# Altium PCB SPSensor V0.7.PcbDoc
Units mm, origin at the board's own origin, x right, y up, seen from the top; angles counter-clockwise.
Board outline 97.48 x 57.45 mm, 2 copper layers (TopLayer, BottomLayer), stack 1.671 mm thick; 111 components, 69 nets, 358 pads, 144 vias.
Unrouted connection lines stored in the file: 1.
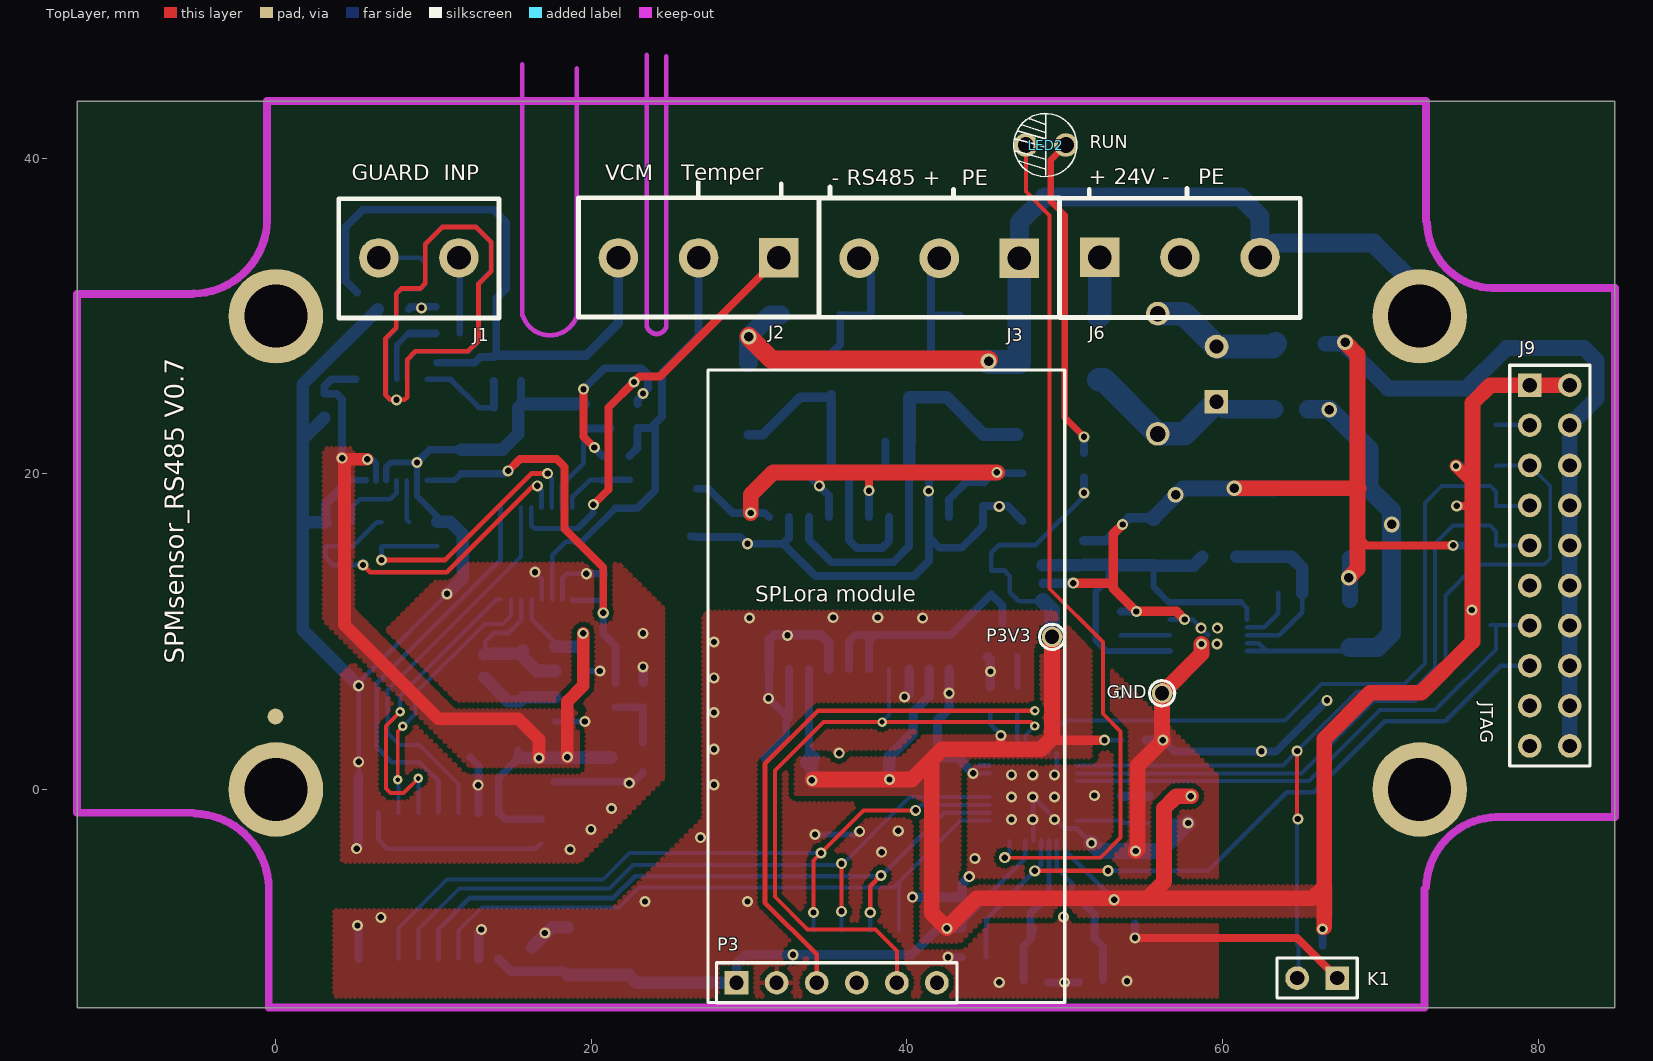
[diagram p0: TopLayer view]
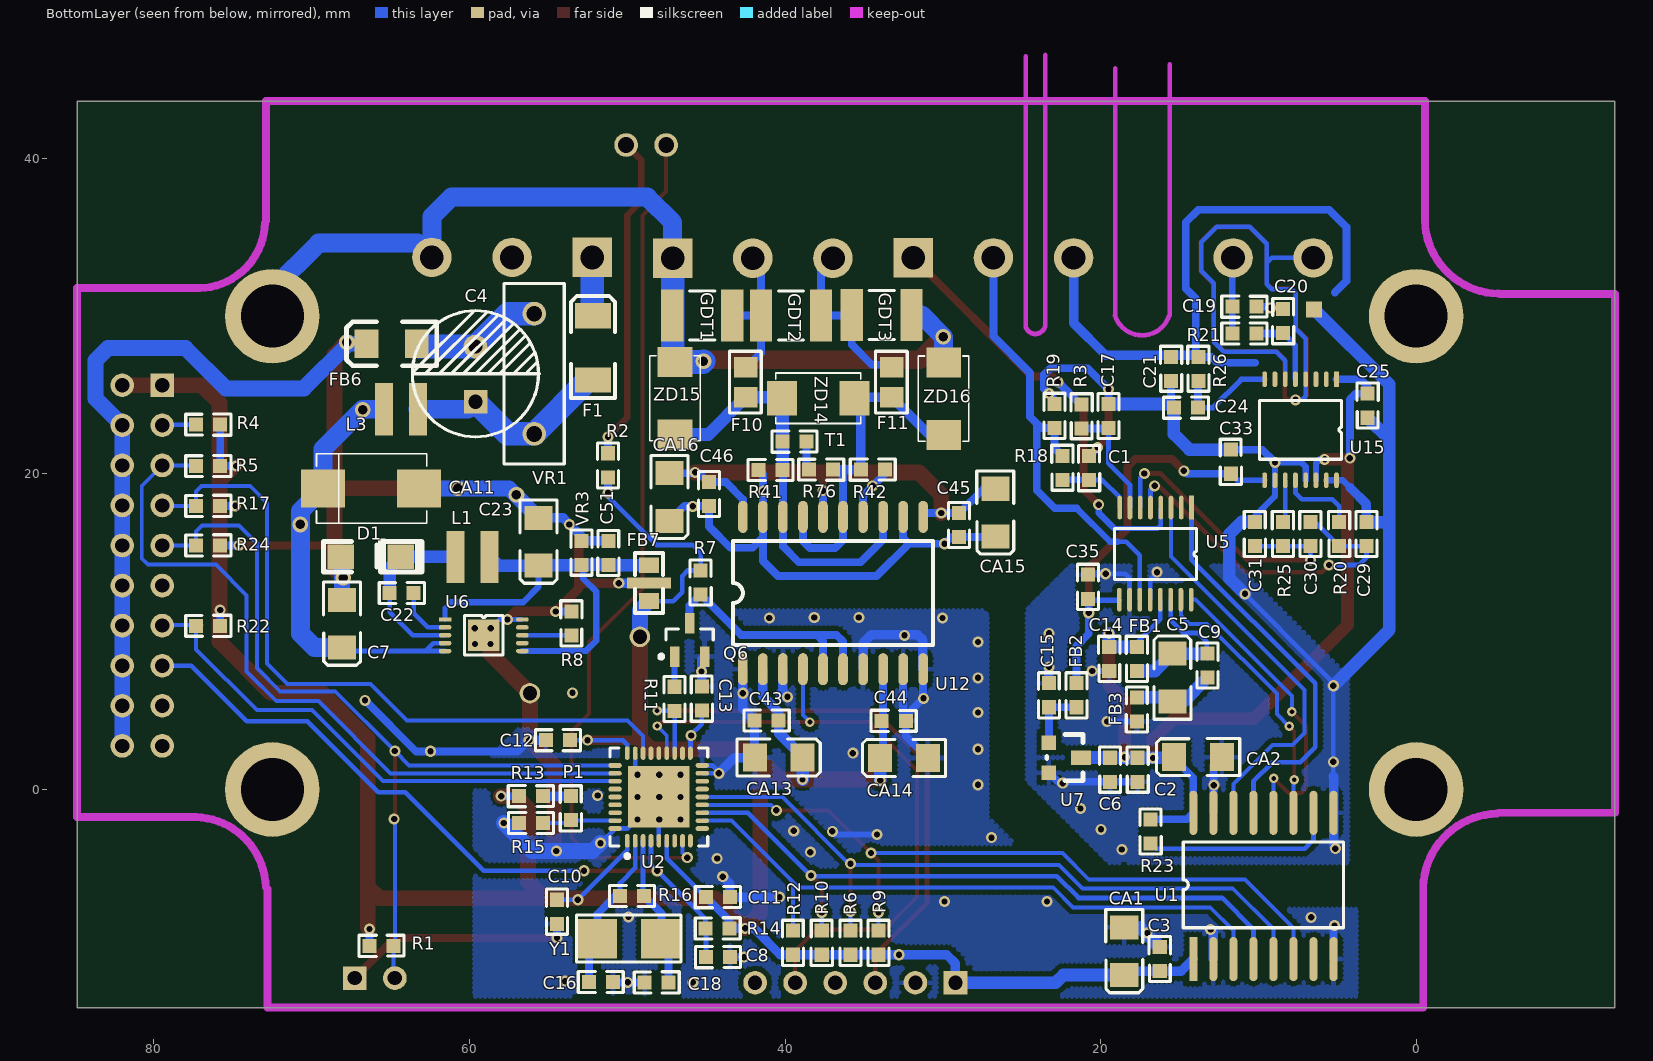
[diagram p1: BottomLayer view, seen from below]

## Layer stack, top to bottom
TopLayer: signal copper 0.0356
Dielectric: core 1.6, FR-4, Dk 4.8
BottomLayer: signal copper 0.0356

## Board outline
-12.6,-13.825 84.875,-13.825 84.875,43.625 -12.6,43.625

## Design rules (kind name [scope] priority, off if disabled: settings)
Clearance Clearance_poly [InPolygon] p1: gap=0.3
Clearance [All] p2: gap=0.15
ComponentClearance [All] p1: gap=0.15 collisioncheckmode=3 verticalgap=0.254 showdistances=FALSE
FabricationTestPointUsage TestPointUsage [All] p1: valid=0 allowmultiple=FALSE
FabricationTestpoint Testpoint [All] p1: side=3 testpointundercomponent=TRUE minsize=1.016 maxsize=2.54 preferedsize=1.524 minholesize=0.508 maxholesize=1.016 preferedholesize=0.813 testpointgrid=0.025 allowsidetop=TRUE allowsidebottom=TRUE usegrid=TRUE gridtolerance=0
HoleSize [All] p1: absolutevalues=TRUE maxlimit=10 minlimit=0.025 maxpercent=80.000 minpercent=20.000
MinimumSolderMaskSliver [All] p1: minsoldermaskwidth=0.15
PlaneClearance [All] p1: clearance=0.2
PlaneConnect [All] p1: planeconnectstyle=Relief reliefexpansion=0.3 reliefentries=4 reliefconductorwidth=0.3 reliefairgap=0.3
PolygonConnect PolygonConnect_via [IsVia] p1: connectstyle=Direct reliefconductorwidth=0.254 reliefentries=4 polygonreliefangle="90 Angle"
PolygonConnect [All] p2: connectstyle=Relief reliefconductorwidth=0.3 reliefentries=4 polygonreliefangle="90 Angle"
RoutingVias [All] p1: holewidth=0.305 width=0.61 viastyle="Through Hole" minholewidth=0.254 minwidth=0.508 maxholewidth=2 maxwidth=5
SilkToSilkClearance [All] p1: silktosilkclearance=0
SilkscreenOverComponentPads [All] p1: minsilkscreentomaskgap=0
SolderMaskExpansion [All] p1: expansion=0.102
Width [All] p1: maxlimit=5.08 minlimit=0.1 preferedwidth=0.254
19 further rules are at their usual default settings.

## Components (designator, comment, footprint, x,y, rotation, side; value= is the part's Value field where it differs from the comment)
C1 "1uF" SM0603 20.775,20.375 r90 bottom
C2 "0.1uF" SM0603 17.6,1.25 r270 bottom
C3 "0.1uF" SM0603 16.2,-10.75 r270 bottom
C4 "100uF/100V" PCAP_3.5_8 59.625,24.575 r90 bottom
C5 "10uF" SM1206 15.45,7.1 r90 bottom
C6 "4.7uF" SM0603 19.35,1.25 r270 bottom
C7 "4.7uF/50V" SM1206 68.075,10.5 r270 bottom
C8 "0.1uF" SM0603 44.25,-10.575 r180 bottom
C9 "0.1uF" SM0603 13.175,7.85 r270 bottom
C10 "0.1uF" SM0603 54.405,-7.75 r270 bottom
C11 "0.1uF" SM0603 44.255,-6.775 r180 bottom
C12 "0.1uF" SM0603 54.4,3.075 r0 bottom
C13 "0.1uF" SM0603 45.33,5.765 r90 bottom
C14 "0.1uF" SM0603 19.4,8.275 r270 bottom
C15 "1uF" SM0603 23.325,5.975 r90 bottom
C16 "22pF" SM0603 51.675,-12.15 r180 bottom
C17 "1uF" SM0603 19.551,23.676 r90 bottom
C18 "22pF" SM0603 48.14,-12.275 r0 bottom
C19 "1uF/50V" SM0603 10.885,30.65 r180 bottom
C20 "1uF/50V" SM0603 8.475,29.69 r90 bottom
C21 "0.1uF" SM0603 15.475,26.66 r270 bottom
C22 "0.47uF" SM0603 64.3,12.4 r0 bottom
C23 "22uF" SM1206 55.625,15.7 r270 bottom
C24 "0.1uF" SM0603 14.59,24.15 r0 bottom
C25 "0.1uF" SM0603 3.025,24.325 r270 bottom
C29 "1uF" SM0603 3.1,16.185 r270 bottom
C30 "100pF" SM0603 6.65,16.185 r270 bottom
C31 "1uF" SM0603 10.275,16.2 r90 bottom
C33 "0.1uF" SM0603 11.8,20.775 r90 bottom
C35 "0.1uF" SM0603 20.85,12.85 r90 bottom
C43 "0.1uF" SM0603 41.175,4.325 r0 bottom
C44 "0.1uF" SM0603 33.11,4.4 r180 bottom
C45 "0.1uF" SM0603 29.025,16.775 r90 bottom
C46 "0.1uF" SM0603 44.775,18.725 r270 bottom
C51 "0.1uF" SM0603 51.25,15 r90 bottom
CA1 "10uF" SM1206 18.5,-10.25 r270 bottom
CA2 "10uF" SM1206 13.825,2.05 r0 bottom
CA11 "47uF/50V" D 69.3,19.075 r180 bottom
CA13 "10uF" SM1206 40.4,2.025 r180 bottom
CA14 "10uF" SM1206 32.465,2 r0 bottom
CA15 "10uF" SM1206 26.675,17.55 r270 bottom
CA16 "10uF" SM1206 47.325,18.535 r270 bottom
D1 "CD1607-B140" 1206D 67.967,14.75 r180 bottom
F1 "1210L005WR" 1808C 52.175,26.088 r90 bottom
F10 "FUSE1" SM0805 42.475,25.8 r90 bottom
F11 "FUSE1" SM0805 33.225,25.8 r90 bottom
FB1 "BLM18PG600SN1" SM0603 17.65,8.275 r270 bottom
FB2 "BLM18PG600SN1" SM0603 21.575,5.975 r90 bottom
FB3 "BLM18PG600SN1" SM0603 17.75,5.075 r90 bottom
FB6 "BLM31PG500SN1" 1206 66.4,28.25 r0 bottom
FB7 "NFM21PC105B1C3" NFM21PC105 48.625,14.225 r270 bottom
GDT1 "SMD1812-091" 1812 45.25,30.05 r180 bottom
GDT2 "SMD1812-091" 1812 39.625,30.05 r0 bottom
GDT3 "SMD1812-091" 1812 33.875,30.075 r180 bottom
GND "TestPoint" "test point" 56.175,6.1 r90 top
J1 "PH2-5.08mm" PH2-5.08mm 6.525,33.7 r0 top locked
J2 "PH3-5.08mm" PH3-5.08mm 31.875,33.7 r180 top
J3 "PH3-5.08mm" PH3-5.08mm 47.125,33.675 r180 top locked
J6 "PH3-5.08mm" PH3-5.08mm 52.225,33.725 r0 top
J9 "JTAG" HDR2X10 79.475,25.625 r270 top
K1 "KEY1" HDR1x2 67.275,-11.955 r180 top (schematic designator R1)
L1 "LPS3010-472ML" LPS3010 60.885,14.75 r180 bottom
L3 "LPS3010-472ML" LPS3010 63.275,24.1 r0 bottom
LED2 "RUN" LED 50.075,40.85 r180 top
P1 "NC" sm0603 53.63,-1.185 r90 bottom
P3 "Header 6" HDR1X6 29.2,-12.25 r0 top
P3V3 "TestPoint" "test point" 49.2,9.675 r90 top
Q6 "MMBT3904" SOT23_N 46.05,9.475 r90 bottom
R1 "10K" SM0603 65.575,-9.855 r180 bottom
R2 "560R" SM0603 51.275,20.55 r90 bottom
R3 "10K" SM0603 21.151,23.651 r270 bottom
R4 "10K" SM0603 76.565,23.075 r0 bottom
R5 "10K" SM0603 76.565,20.45 r0 bottom
R6 "100K" SM0603 35.901,-9.713 r90 bottom
R7 "4.7K" SM0603 45.4,13.125 r90 bottom
R8 "49.9K" SM0603 53.5,10.525 r270 bottom
R9 "100K" SM0603 34.126,-9.713 r90 bottom
R10 "100K" SM0603 37.726,-9.713 r90 bottom
R11 "1K" SM0603 47.055,5.75 r90 bottom
R12 "100K" SM0603 39.551,-9.713 r90 bottom
R13 "1K" SM0603 56.105,-0.375 r180 bottom
R14 "10K" SM0603 44.275,-8.85 r0 bottom
R15 "100K" SM0603 56.09,-2.075 r180 bottom
R16 "10M" SM0603 49.7,-6.7 r180 bottom
R17 "10K" SM0603 76.565,17.925 r0 bottom
R18 "10K" SM0603 22.375,20.385 r270 bottom
R19 "5K,0.1%" SM0603 22.875,23.675 r270 bottom
R20 "10K" SM0603 4.825,16.185 r270 bottom
R21 "10M" SM0603 10.885,28.95 r180 bottom
R22 "10K" SM0603 76.565,10.325 r0 bottom
R23 "4.7K" SM0603 16.875,-2.65 r90 bottom
R24 "NC" SM0603 76.565,15.425 r0 bottom
R25 "10K" SM0603 8.4,16.185 r270 bottom
R26 "10K" SM0603 13.75,26.66 r270 bottom
R41 "47K" SM0603 40.91,20.3 r180 bottom
R42 "47K" SM0603 34.435,20.325 r180 bottom
R76 "120R" SM0603 37.715,20.225 r0 bottom
T1 "" SM0603 39.4,22.1 r180 bottom
U1 "ADuM5401ARWZ" ADUM1401 14.125,-10.75 r90 bottom
U2 "STM32F103TBU6" VFQN36_V 48,-0.475 r90 bottom locked
U5 "AD7793BRU" AD7793 16.525,14.95 r270 bottom
U6 "LT3971IMSE-3.3" LT3971 59.1,9.775 r270 bottom
U7 "AD1584BRTZ" SOT-23 21.13,0.639 r270 bottom
U12 "ADM2587E" SOL-20 42.675,7.625 r90 bottom
U15 "LMP91200" LMP91200 7.325,22.8 r0 bottom
VR1 "14D101K" RAD-0.3 55.9,26.35 r90 bottom
VR3 "V3.5MLA0603N" SM0603 52.85,15 r270 bottom (schematic designator VA2)
Y1 "8MHz" CY5.4X4.6 51.875,-9.45 r180 bottom
ZD14 "SMBJ12" ZD 40.2,24.8 r180 bottom (schematic designator ZD16)
ZD15 "SMBJ12" ZD 46.975,22.5 r90 bottom
ZD16 "SMBJ12" ZD 29.95,27.075 r270 bottom

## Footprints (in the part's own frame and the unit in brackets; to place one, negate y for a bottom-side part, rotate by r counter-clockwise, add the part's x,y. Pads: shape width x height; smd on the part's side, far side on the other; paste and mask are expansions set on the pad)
1206 [mm]
  rect 1.5x1.8 smd: 1(-3.048,0) 2(0.127,0)
  silkscreen extent -4.32,-1.4 1.4,1.4
1206D [mm]
  rect 1.7x1.524 smd: 1(-0.19,0.003) 2(3.61,0.003)
  silkscreen extent -1.3,-0.97 4.96,0.99
1808C [mm]
  rect 1.6x2.3 smd: 1(3.937,0) 2(-0.127,0)
  silkscreen extent -1.27,-1.4 5.21,1.4
1812 [mm] "Chip Capacitor, Body 4.5x3.2mm, IPC High Density"
  rect 1.4x3.3 smd: 1(-1.9,0) 2(1.9,0)
  silkscreen extent -0.8,-1.55 0.8,1.55, body extent -2.4,-1.7 2.4,1.7, height 1.4
AD7793 [mm]
  rect 1.5x0.3 smd: 1(-2.921,2.286)
  oval 1.5x0.3 smd: 2(-2.921,1.636) 3(-2.921,0.986) 4(-2.921,0.336) 5(-2.921,-0.314) 6(-2.921,-0.964) 7(-2.921,-1.614) 8(-2.921,-2.264) 9(2.921,-2.286) 10(2.921,-1.636) 11(2.921,-0.986) 12(2.921,-0.336) 13(2.921,0.314) 14(2.921,0.964) 15(2.921,1.614) 16(2.921,2.264)
  silkscreen extent -1.59,-2.59 1.64,2.61
ADUM1401 [mm]
  rect 2.8x0.51 smd: 1(0,0)
  oval 2.8x0.51 smd: 2(0,-1.27) 3(0,-2.54) 4(0,-3.81) 5(0,-5.08) 6(0,-6.35) 7(0,-7.62) 8(0,-8.89) 9(9.271,-8.89) 10(9.271,-7.62) 11(9.271,-6.35) 12(9.271,-5.08) 13(9.271,-3.81) 14(9.271,-2.54) 15(9.271,-1.27) 16(9.271,0)
  silkscreen extent 1.99,-9.53 7.43,0.63
CY5.4X4.6 [mm]
  rect 2.5x2.5 smd: 1(-0.025,0) 2(4,0)
  silkscreen extent -1.35,-1.49 5.28,1.49
D [mil]
  rect 110x94.49 smd: 1(0,0) 2(240,0)
  silkscreen extent -16,-87 260,87
HDR1x2 [mm] "Connector; Header; 2 Position"
  rect 1.5x1.5 hole 0.9: 1(0,0)
  round 1.5 hole 0.9: 2(2.54,0)
  silkscreen extent -1.27,-1.27 3.81,1.27
HDR1X6 [mm] "Connector; Header; 6 Position"
  rect 1.5x1.5 hole 0.9: 1(0,0)
  round 1.5 hole 0.9: 2(2.54,0) 3(5.08,0) 4(7.62,0) 5(10.16,0) 6(12.7,0)
  silkscreen extent -1.27,-1.27 13.97,1.27
HDR2X10 [mm] "Connector; Header; 10x2 Position"
  rect 1.5x1.5 hole 0.9: 1(0,0)
  round 1.5 hole 0.9: 2(0,2.54) 3(2.54,0) 4(2.54,2.54) 5(5.08,0) 6(5.08,2.54) 7(7.62,0) 8(7.62,2.54) 9(10.16,0) 10(10.16,2.54) 11(12.7,0) 12(12.7,2.54) 13(15.24,0) 14(15.24,2.54) 15(17.78,0) 16(17.78,2.54) 17(20.32,0) 18(20.32,2.54) 19(22.86,0) 20(22.86,2.54)
  silkscreen extent -1.27,-1.27 24.13,3.81
LED [mm]
  round 1.5 hole 1: 1(0,0) 2(2.54,0)
  silkscreen extent -0.7,-2 3.3,2
LMP91200 [mm]
  rect 0.3x1 smd: 1(-2.275,-3.2)
  oval 0.3x1 smd: 2(-1.625,-3.2) 3(-0.975,-3.2) 4(-0.325,-3.2) 5(0.325,-3.2) 6(0.975,-3.2) 7(1.625,-3.2) 8(2.275,-3.2) 9(2.275,3.2) 10(1.625,3.2) 11(0.975,3.2) 12(0.325,3.2) 13(-0.325,3.2) 14(-0.975,3.2) 15(-1.625,3.2) 16(-2.275,3.2)
  silkscreen extent -2.6,-1.87 2.6,1.87
LPS3010 [mm]
  rect 1.14x3.3 smd: 1(0,0) 2(2.16,0)
LT3971 [mm]
  rect 0.28x0.8 smd: 1(-1,-2.45)
  oval 0.28x0.8 smd: 2(-0.5,-2.45) 3(0,-2.45) 4(0.5,-2.45) 5(1,-2.45) 6(1,2.45) 7(0.5,2.45) 8(0,2.45) 9(-0.5,2.45) 10(-1,2.45)
  rect 2x2 smd: 11(0,0)
  silkscreen extent -1.25,-1.21 1.25,1.22
NFM21PC105 [mm]
  rect 1x1.27 smd: 1(0.01,0.008) 2(2.286,0)
  rect 0.7x2.8 smd: 3(1.143,0)
  silkscreen extent -0.76,-0.89 3.05,0.89
PCAP_3.5_8 [mm]
  rect 1.5x1.5 hole 0.9: 1(0.001,-0.009)
  round 1.5 hole 0.9: 2(3.5,0)
  silkscreen extent -2.22,-4.06 5.78,4
PH2-5.08mm [mm]
  round 2.5 hole 1.5: 1(0,0) 2(5.08,0)
  silkscreen extent -2.54,-3.81 7.62,3.75
PH3-5.08mm [mm]
  rect 2.5x2.5 hole 1.5: 1(0,0)
  round 2.5 hole 1.5: 2(5.08,0) 3(10.16,0)
  silkscreen extent -2.54,-3.81 12.7,3.75
RAD-0.3 [mm] "Radial Cap, Thru-Hole; 2 Leads; 0.3 in Pin Spacing"
  round 1.5 hole 1: 1(-3.81,0) 2(3.81,0)
  silkscreen extent -5.71,-1.91 5.71,1.91
SM0603 [mil]
  rect 35x35 smd: 1(-30,-2) 2(30,-2)
  silkscreen extent -57,-28 56,24
sm0603 [mil]
  rect 35x35 smd: 1(-30,-2) 2(30,-2)
  silkscreen extent -57,-28 56,24
SM0805 [mm]
  rect 1.3x1.5 smd: 1(-0.933,0.022) 2(0.967,0.022)
  silkscreen extent -1.93,-0.97 1.98,1.04
SM1206 [mil]
  rect 60x70 smd: 1(59.5,0) 2(-59.5,0)
  silkscreen extent -104,-46 104,46
SOL-20 [mil]
  oval 80x24 smd: 1(0,0) 2(0,-50) 3(0,-100) 4(0,-150) 5(0,-200) 6(0,-250) 7(0,-300) 8(0,-350) 9(0,-400) 10(0,-450) 11(380,-450) 12(380,-400) 13(380,-350) 14(380,-300) 15(380,-250) 16(380,-200) 17(380,-150) 18(380,-100) 19(380,-50) 20(380,0)
  silkscreen extent 60,-475 320,25
SOT23_N [mm] "SOT23, 3-Leads, Body 2.9x1.3mm, Pitch 0.95mm, Lead Span 2.3mm, IPC Medium Density"
  rect 1.3x0.6 smd: 1(-1.05,0.95) 2(-1.05,-0.95) 3(1.05,0)
  silkscreen extent -1.17,-1.5 0.7,1.93, body extent -0.7,-1.5 0.7,1.5, height 1.1
SOT-23 [mil]
  rect 36x36 smd: 1(-91.86,-84.66) 2(-16.86,-84.66)
  rect 36x50 smd: 3(-53.86,-4.66)
  silkscreen extent -112,-90 3,0
"test point" [mm]
  round 1.3 hole 0.9: 1(0,0)
  silkscreen extent -0.8,-0.8 0.8,0.8
VFQN36_V [mm] "QFN, 36-Leads, Body 6x6mm, Pitch 0.5mm, ST Recommended"
  oval 0.85x0.3 smd: 1(-2.775,2) 2(-2.775,1.5) 3(-2.775,1) 4(-2.775,0.5) 5(-2.775,0) 6(-2.775,-0.5) 7(-2.775,-1) 8(-2.775,-1.5) 9(-2.775,-2) 19(2.775,-2) 20(2.775,-1.5) 21(2.775,-1) 22(2.775,-0.5) 23(2.775,0) 24(2.775,0.5) 25(2.775,1) 26(2.775,1.5) 27(2.775,2)
  oval 0.3x0.85 smd: 10(-2,-2.755) 11(-1.5,-2.755) 12(-1,-2.755) 13(-0.5,-2.755) 14(0,-2.755) 15(0.5,-2.755) 16(1,-2.755) 17(1.5,-2.755) 18(2,-2.755) 28(2,2.775) 29(1.5,2.775) 30(1,2.775) 31(0.5,2.775) 32(0,2.775) 33(-0.5,2.775) 34(-1,2.775) 35(-1.5,2.775) 36(-2,2.775)
  rect 3.9x3.9 smd: 37(0,0)
  silkscreen extent -3.87,-3.1 3.1,3.1, body extent -3.05,-3.05 3.05,3.05, height 1
ZD [mm]
  rect 1.9x2.2 smd: 1(0,0) 2(4.6,0)
  silkscreen extent -0.4,-1.6 5,1.6

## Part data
C1 C6 C7 C9 C14 C15 C17 C19 C20 C21 C22 C24 C25 C29 C30 C31 C33 C35 C51: library part CAP, "Capacitor"
C2 C3 C43 C44 C45 C46: library part CA, "电容"
C4: library part C, "Capacitor"
C5 CA11 CA13 CA14 CA15 CA16: library part CAPE, "极性电容"
C8: library part Cap, "Capacitor, X7R Ceramic"
C10 C11 C12 C13 C16 C18: library part Cap, "Capacitor"
C23: library part C, "极性电容"
CA1 CA2: library part CAPE, "Capacitor"
D1: library part DIODE, "Diode"
F1: library part FUSE1, "Fuse, 50mA"
F10 F11: "Fuse"
FB1 FB3 L1 L3: library part INDUCTOR
FB2 FB6 FB7: library part Inductor, "Inductor"
GDT1 GDT2 GDT3: library part BT90
J1 K1: library part "Header 2", "Header, 2-Pin"
J2 J3 J6: library part CON3, "Connector"
J9: library part "Header 10X2", "Header, 10-Pin, Dual row"
LED2: library part LED0, "Typical INFRARED GaAs LED"
P1: library part Header, "Header, 2-Pin, 2.54mm, 排针"
P3: "Header, 6-Pin"
Q6: "NPN Switching Transistor"
R1 R2 R7 R11 R16: library part Res2, "Resistor"
R3 R4 R5 R6 R9 R10 R12 R17 R18 R19 R20 R22 R24 R25 R26: library part RES, "电阻"
R8 R13 R14 R15 R23 R41 R42 R76: library part RE, "电阻"
R21: library part RES, "resistor"
T1: library part CON2, "Connector"
U1: library part ADUM1401, "1Mbps Data Rate, 100ns Propagation delay"
U2: library part STM32F103T8U6, "STM32 ARM-based 32-bit MCU with 64 Kbytes Flash, 36-pin VFQFPN, Industrial Temperature"
U5: library part AD7793
U6: library part LT3971
U7: library part "Header 3", "4.096V reference"
VR1: library part "Res Varistor", "Varistor (Voltage-Sensitive Resistor)"
VR3: library part "D Zener", "Zener Diode"
Y1: library part XTAL, "Crystal Oscillator"
ZD14 ZD15 ZD16: library part SMBJ, "瞬变抑制二极管"

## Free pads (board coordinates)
  round 1 smd: 0(-0.025,4.625)
  rect 1x1 smd far side: 0(6.475,30.425)
  round 6 hole 4: 3(72.5,30) 4(72.5,0) 5(0,0) 6(0,30)

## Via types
v1: diameter 0.7, hole 0.4, TopLayer to BottomLayer, 129 vias
v2: diameter 1, hole 0.6, TopLayer to BottomLayer, 8 vias
v3: diameter 0.6, hole 0.3, TopLayer to BottomLayer, 7 vias

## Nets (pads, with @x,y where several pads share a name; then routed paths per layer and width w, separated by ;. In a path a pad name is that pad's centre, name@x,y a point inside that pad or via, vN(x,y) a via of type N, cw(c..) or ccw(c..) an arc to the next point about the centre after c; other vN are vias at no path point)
24VGND_IN: J6.2 | length 1
  BottomLayer w1.5: J6.2@56.975,33.395 J6.2 J6.2@57.647,33.383
+24V: C7.1 CA11.1 L3.2 U6.4 U6.5 | length 28.3
  BottomLayer w0.3: U6.5 62.8,8.775 ; U6.4 62.3,9.275 62.8,8.775 ; C7.1 67.861,8.775 62.8,8.775
  BottomLayer w1.2: L3.2 66.775,24.1 69.3,21.575 CA11.1 70.725,17.65 v2(70.725,16.8) 70.725,9.9 69.814,8.989 C7.1
  other v2: 66.775,24.075
+24V_IN: F1.1 J6.1 | length 3.8
  BottomLayer w1.5: F1.1 52.225,30.075 J6.1 J6.1@52.175,33.675
BOOT0: P1.1 R15.2 U2.35 | length 4.6
  BottomLayer w0.25: U2.35 53.552,-1.975 P1.1 53.758,-2.126 R15.2
DE485: Q6.3 R7.1 U12.5 U12.6 | length 16.5
  BottomLayer w0.5: U12.6 36.325,9.375 36.75,9.8 38,9.8 ; U12.5 37.595,9.395 38,9.8 ; Q6.3 46.05,11.662 R7.1 42.786,9.8 38,9.8
DVDD: C5.1 C9.1 FB1.2 U5.14 | length 10.1
  BottomLayer w0.3: C9.1@13.275,8.611 13.275,9.35 13.85,9.925 14.75,9.925 15.561,10.736 U5.14
  BottomLayer w0.8: C9.1@13.226,8.562 13.275,8.611 C5.1 ; C5.1@15.663,8.824 C5.1 ; FB1.2 16.548,7.513 C5.1
EARTH: GDT1.1 GDT3.2 J3.1 J6.3 pad.3 ZD15.2 ZD16.1 | length 63.5
  TopLayer w1.2: v2(29.975,28.7) 31.438,27.237 v2@45.175,27.237
  BottomLayer w1.2: ZD16.1 29.95,28.675 v2(29.975,28.7) 31.35,30.075 GDT3.2 ; ZD15.2@46.725,27.35 ZD15.2 ; J3.1 47.125,35.95 48.725,37.55 61.15,37.55 62.385,36.315 J6.3 63.296,34.636 66.7,34.636 69.564,34.636 72.5,31.7 pad.3
  BottomLayer w1.5: v2(45.175,27.15) 45.225,27.1 ZD15.2 ; ZD15.2@47.125,27.1 J3.1 J3.1@47.175,33.625
GND: C3.1 C7.2 C8.2 C10.2 C11.2 C12.2 C13.2 C16.2 C18.2 C23.2 C43.2 C44.2 C51.2 CA1.2 CA11.2 CA13.2 CA14.2 D1.1 FB6.2 FB7.3 GND.1 J9.4 J9.6 J9.8 J9.10 J9.12 J9.14 J9.16 J9.18 J9.20 K1.1 P3.2 Q6.2 R8.1 R15.1 R24.1 U1.2 U1.8 U2.5 U2.17 U2.18 U2.26 U2.36 U2.37 U6.10 U6.11 U12.1 U12.3 U12.7 U12.9 U12.10 VR3.1 | length 219.2
  TopLayer w0.3: v1@51.85,-0.375 v1(51.875,-0.375)
  TopLayer w0.5: v1(54.456,-9.406) 64.726,-9.406 K1.1 ; 68.55,16.075 69.149,15.476 v1(74.625,15.476)
  TopLayer w0.6: v1(50.543,13.082) 53.068,13.082 ; v1(53.675,16.8) 53.068,16.193 53.068,13.082 ; v1(57.6,10.775) 57.088,11.287 v1(54.538,11.287) 53.068,12.757 53.068,13.082
  TopLayer w1: v1(54.5,-3.9) 54.625,-3.775 54.625,1.527 v1(56.224,3.126) 56.175,3.175 GND.1 58.675,8.6 v1(58.675,9.225) ; v2(60.75,19.1) 68.55,19.1 ; v2(67.775,28.35) 68.55,27.575 68.55,19.1 ; v2(68,13.425) 68.55,13.975 68.55,16.075 68.55,19.1 ; 68.625,19.1 68.55,19.1
  BottomLayer w0.3: v1@44.15,1.075 44.6,1.525 U2.18 ; v1(44.2,1.025) U2.17 ; U2.5 U2.37 50,-2.475 U2.36 v1(51.7,-3.4) ; U2.37@49.5,1.025 U2.26 ; U6.10 58.1,10.775 U6.11
  BottomLayer w0.4: v1(34.175,-2.85) 36.8,-2.85 v1(37,-2.65)
  BottomLayer w0.5: U1.8 v1@5.235,-8.685 ; CA14.2 32.348,3.395 C44.2 C44.2@32.515,4.516 ; U12.10 31.245,5.786 C44.2@32.515,4.516 ; U12.9 C44.2@32.515,4.516 ; v1(42.601,-10.626) C8.2 ; C18.2 v1(49.975,-12.224) 50.89,-12.224 C16.2 ; R8.1 v1(54.538,11.287) ; v1(54.456,-9.406) C10.2 ; v1(56.224,3.126) 56.95,2.4 63.375,2.4 v1(66.625,5.65) ; v1(74.625,15.476) R24.1
  BottomLayer w0.6: U1.2 12.855,-9.045 v1(13.025,-8.875) ; U12.10@31.265,7.625 31.265,9.465 31.6,9.8 34.55,9.8 35.055,9.295 U12.7 ; v1(39.85,5.875) 39.95,5.875 40.135,6.06 U12.3 ; v1(40.351,-6.826) C11.2 43.493,-5.982 v1(43.95,-5.525) ; U12.1 42.675,5.114 C43.2 41.937,2.05 CA13.2 43.2,2.025 44.15,1.075 v1(44.2,1.025) ; Q6.2 45.279,8.246 C13.2 ; FB7.3 v1(50.543,13.082) ; C51.2 52.612,15.762 54.061,17.211 C23.2 ; C12.2 v1(56.224,3.126) ; R15.1 v1(57.826,-2.126)
  BottomLayer w0.8: C3.1 17.5,-8.739 CA1.2
  BottomLayer w1: v1(51.7,-3.4) 52.2,-3.9 v1(54.5,-3.9) 56.052,-3.9 v1(57.826,-2.126) ; C23.2 57.489,19.075 CA11.2 ; FB6.2 v2@67.675,28.25 ; v2(67.775,28.35) v2@67.675,28.25 ; C7.2 D1.1@68.075,14.67 ; J9.20 J9.18 J9.16 J9.14 J9.12 J9.10 J9.8 J9.6 J9.4 83.7,24.77 83.7,27.2 82.925,27.975 78,27.975 75.45,25.425 70.5,25.425 v2@67.675,28.25
  other v1: 45.85,-12.225 53.95,-12.15 17.05,-9.1 5.175,-8.625 6.65,-8.1 49.925,-8.075 23.4,-7.1 29.9,-7.1 44.3,-4.375 38.4,-3.975 26.919,-3.05 39.45,-2.625 46.625,-1.9 47.975,-1.9 49.35,-1.9 46.625,-0.475 47.975,-0.475 49.35,-0.475 27.775,0.3 46.625,0.925 47.975,0.925 49.35,0.925 35.7,2.3 62.475,2.425 27.775,2.55 27.775,4.875 31.225,5.775 42.675,6.1 53.475,6.125 27.775,7.075 45.3,7.475 59.65,9.225 27.775,9.35 32.425,9.775 58.65,10.225 59.675,10.225 30.025,10.875 41,10.875 35.325,10.9 38.15,10.9
  other v2: 57.025,18.675
GND_COM: C45.2 C46.1 CA15.2 CA16.2 R42.2 U12.11 U12.14 U12.16 U12.20 | length 36.2
  TopLayer w0.5: v1(34.45,19.25) 34.45,20.025 ; v1(37.595,18.945) 37.595,20.03
  TopLayer w1: v1(30.1,17.525) 30.1,18.675 31.525,20.1 v1(45.7,20.1)
  BottomLayer w0.5: CA15.2 27.414,19.061 28.938,17.537 C45.2 30.985,17.537 U12.11 ; R42.2 33.673,20.002 35.055,18.62 U12.14 ; U12.16 v1(37.595,18.945) ; U12.20 42.675,18.4 43.762,19.487 C46.1 ; C46.1@44.851,19.462 45.435,20.047 CA16.2
GND_ISO: C1.2 C2.2 C6.2 C14.2 C15.2 C17.2 C19.2 C20.2 C21.2 C24.2 C25.2 C29.1 C31.2 C33.2 C35.2 CA2.2 FB3.1 pad.0@6.475,30.425 R19.1 U1.9 U1.15 U5.10 U5.12 U7.2 U15.10 U15.13 U15.15 U15.16 | length 119.2
  TopLayer w0.5: v1(19.501,25.376) 19.501,22.36 v1(20.186,21.675)
  BottomLayer w0.3: 5.25,0.825 v1(5.25,1.75) v1(5.25,6.575) 5.25,6.775 11.976,13.501 11.976,15.413 11.85,15.413 ; v1(16.425,13.775) 16.861,13.339 U5.12 ; U5.10 18.161,13.386 18.45,13.675 v1(19.675,13.675)
  BottomLayer w0.4: 4.175,19.125 4.65,19.6 U15.16 U15.15 ; U15.13 7,20.45 7.275,20.725 v1(8.95,20.725) U15.10 8.95,18.575 10.224,17.301 C31.2 ; FB3.1 v1(19.587,4.313) ; C14.2 v1(20.538,7.513)
  BottomLayer w0.5: C20.2 8.572,30.599 C19.2 ; v1(8.95,20.725) 9.762,21.537 C33.2 ; CA2.2 12.855,1.509 U1.15 ; C24.2@15.526,24.375 C21.2 ; C2.2 C6.2 22.702,0.488 U7.2 ; C17.2 v1@19.5,25.375 ; v1(19.501,25.376) 20.825,26.7 23.175,26.7 23.575,26.3 23.575,25.4 v1(23.276,25.101) 23.276,25.051 22.926,24.701 R19.1 ; v1(19.675,13.675) C35.2@20.799,13.675 ; v1(20.186,21.675) C1.2 ; C35.2 C35.2@20.811,13.6
  BottomLayer w0.6: C29.1 3.151,18.101 4.175,19.125 ; v1(5.125,-3.75) 5.235,-3.64 U1.9 5.235,0.81 5.25,0.825 ; C15.2@23.274,6.787 v1(23.274,7.774)
  BottomLayer w0.8: C25.2 1.7,22.187 ; C29.1 1.997,16.947 1.7,16.65 ; v1(5.25,6.575) 1.7,10.125 1.7,16.65 ; pad.0@6.462,30.437 1.7,25.675 1.7,22.187 ; C31.2 11.063,16.962 11.85,16.175 11.85,15.413 11.85,13.4 v1(10.85,12.4) ; C33.2 14.362,21.537 15.352,22.527 C24.2 15.526,24.375 15.589,24.438 C17.2 ; 1.7,16.65 1.7,22.187
  other v1: 18.65,-3.8 19.975,-2.525 21.275,-1.2 12.825,0.275 22.4,0.4 23.275,9.9 9.225,30.525
GUARD: J1.1 U15.4 U15.6 | length 65
  TopLayer w0.3: 6.95,25 7.25,24.7 v1(7.65,24.7) 8.15,24.7 8.325,24.875 8.325,27.25 8.85,27.775 12.175,27.775 12.85,28.45 12.85,32.05 13.65,32.85 13.65,34.7 12.7,35.65 10.55,35.65 9.475,34.575 9.475,32.075 9.15,31.75 7.95,31.75 7.625,31.425 7.625,29.275 6.95,28.6 6.95,25
  BottomLayer w0.3: J1.1 9.15,33.7 9.475,33.375 ; v1(7.65,24.7) 7.225,24.7 7,24.925 U15.4 7,28.575 7.625,29.2 7.625,31.45 7.875,31.7 9.15,31.7 9.475,32.025 9.475,33.375 ; U15.6 8.3,27.175 8.875,27.75 12.2,27.75 12.825,28.375 12.825,32.075 13.625,32.875 13.625,34.675 12.625,35.675 10.55,35.675 9.475,34.6 9.475,33.375
JNTRST: J9.3 R4.2 | length 2.2
  BottomLayer w0.3: R4.2 79.434,23.126 J9.3
JTCK: J9.9 K1.2 R1.2 R24.2 U2.28 | length 55.1
  TopLayer w0.25: v1(64.735,2.435) 64.735,-1.835 v1(64.775,-1.875)
  BottomLayer w0.25: U2.28 63.825,1.525 v1(64.735,2.435) 68.525,6.225 72,6.225 73.475,7.7 73.475,15.6 74.6,16.725 76.95,16.725 77.327,16.348 R24.2 77.338,15.465 J9.9 ; K1.2 64.813,-11.877 R1.2 64.735,-9.828 v1@64.735,-1.875
JTDI: J9.5 R5.2 U2.29 | length 47.1
  BottomLayer w0.25: U2.29 65,1.025 69.575,5.6 72.25,5.6 74.125,7.475 74.125,12.3 76.075,14.25 80.375,14.25 80.775,14.65 80.775,19.245 J9.5 77.371,20.545 R5.2
JTDO: J9.13 R22.2 U2.30 | length 34
  BottomLayer w0.25: U2.30 65.475,0.525 69.975,5.025 73.477,5.025 77.327,8.875 R22.2 ; R22.2@77.002,10.426 79.434,10.426 J9.13
JTMS: J9.7 R17.2 U2.25 | length 45.2
  BottomLayer w0.25: U2.25 49,3.4 49.975,4.375 63.95,4.375 66.275,6.7 71.55,6.7 72.825,7.975 72.825,18.15 73.9,19.225 77,19.225 77.327,18.898 R17.2 79.446,17.976 J9.7
JTRST: U2.31
KEY1: U2.24
LED_S1: U2.23
LED_S2: LED2.2 U2.8 | length 55.5
  TopLayer w0.25: v1(46.2,-4.325) 52.275,-4.325 53.55,-3.05 53.55,3.675 52.425,4.8 52.425,9.35 49.05,12.725 49.05,36.375 47.535,37.89 LED2.2
  BottomLayer w0.25: v1(46.2,-4.325) 46.5,-4.025 U2.8
LORA_AUX: P3.6
MCU_RXD1: P3.5 U2.22 U12.4 | length 42.5
  TopLayer w0.25: P3.5 39.36,-10.235 38,-8.875 33.7,-8.875 31.625,-6.8 31.625,1.2 34.7,4.275 47.85,4.275 v3(48.1,4.025)
  BottomLayer w0.25: v3(38.425,4.275) 38.865,4.715 U12.4 ; U2.22 47.5,3.425 v3(48.1,4.025)
MCU_TXD1: P3.3 R11.1 U2.21 | length 37.5
  TopLayer w0.3: P3.3 34.28,-10.455 31,-7.175 31,1.625 34.363,4.988 v3(48.113,4.988)
  BottomLayer w0.3: U2.21 R11.1@47,4.983 ; R11.1 v3(48.113,4.988)
MISO1: R9.2 U1.6 U2.13 | length 47.8
  TopLayer w0.25: v1(34.075,-7.8) 34.075,-4.5 v1(34.55,-4.025) 37.25,-1.325 v1(40.55,-1.325)
  BottomLayer w0.25: U1.6 7.775,-8.775 10.85,-5.7 20.75,-5.7 22.425,-4.025 v1(34.55,-4.025) ; R9.2 v1(34.075,-7.8) ; v1(40.55,-1.325) 40.9,-0.975 U2.13
MOSI1: R6.2 U1.5 U2.14 | length 45.8
  TopLayer w0.25: v1(35.85,-7.725) v1(35.85,-4.7)
  BottomLayer w0.25: U1.5 9.045,-8.855 11.625,-6.275 21.15,-6.275 22.65,-4.775 35.875,-4.775 40.175,-0.475 U2.14 ; R6.2 v1(35.85,-7.725)
NetC1_1: C1.1 R18.2 U5.8 | length 4.8
  BottomLayer w0.3: U5.8 18.789,18.514 19.888,19.613 C1.1
  BottomLayer w0.4: C1.1@20.724,19.564 C1.1 20.734,19.623 R18.2
NetC4_1: C4.1 F1.2 L3.1 VR1.1 | length 13.6
  BottomLayer w1.2: C4.1 60.092,24.1 L3.1
  BottomLayer w1.5: F1.2 52.479,25.961 VR1.1 57.581,22.54 C4.1
NetC4_2: C4.2 FB6.1 VR1.2 | length 8.4
  BottomLayer w1.5: VR1.2 57.54,30.16 C4.2 63.177,28.075 FB6.1
NetC5_2: C5.2 C9.2 FB3.2 | length 5.2
  BottomLayer w0.8: C9.2 14.725,5.589 C5.2 15.698,5.837 FB3.2
NetC15_1: C15.1 FB2.1 U7.1 | length 4
  BottomLayer w0.5: FB2.1 C15.1 23.274,2.978 U7.1
NetC16_1: C16.1 R16.1 U2.2 Y1.1 | length 9.9
  BottomLayer w0.3: U2.2 49.5,-4.97 50.462,-5.932 R16.1
  BottomLayer w0.5: R16.1@50.751,-6.751 51.9,-7.9 Y1.1 52.437,-9.987 C16.1@52.437,-12.076
NetC17_1: C17.1 R3.2 U5.7 | length 7.1
  BottomLayer w0.3: U5.7 18.139,19.314 19.5,20.675 C17.1@19.5,22.814 ; C17.1@19.629,22.904 C17.1@19.644,22.919
  BottomLayer w0.5: C17.1@19.629,22.904 19.645,22.889 R3.2
NetC18_1: C18.1 R16.2 U2.3 Y1.2 | length 10.2
  BottomLayer w0.3: R16.2@49,-6.689 U2.3
  BottomLayer w0.5: C18.1@47.378,-12.099 47.378,-9.947 Y1.2 Y1.2@48.025,-8.814 ; Y1.2@47.838,-9.413 47.838,-7.851 R16.2@49,-6.689
NetC20_1: C20.1 R21.2 U15.5 | length 4.9
  BottomLayer w0.35: U15.5 7.65,28.154 C20.1
  BottomLayer w0.5: C20.1@8.453,28.899 R21.2
NetC22_1: C22.1 U6.2 | length 3.6
  BottomLayer w0.3: U6.2 62.65,10.275 63.538,11.163 C22.1
NetC22_2: C22.2 D1.2 L1.1 U6.3 | length 11.4
  BottomLayer w0.3: U6.3 63.6,9.775 65.062,11.237 C22.2
  BottomLayer w0.8: L1.1 60.888,14.753 D1.2 65.062,14.048 C22.2
NetC23_1: C23.1 C51.1 FB7.1 L1.2 U6.1 U6.6 VR3.2 | length 28.4
  BottomLayer w0.3: 61.175,11.875 61.55,11.5 U6.1
  BottomLayer w0.4: VR3.2@52.787,14.201 52.787,13.362 51.975,12.55 51.975,9.425 52.625,8.775 U6.6 ; C23.1 55.625,12.85 56.6,11.875 61.175,11.875
  BottomLayer w0.8: FB7.1 C51.1@50.851,14.215 ; C51.1 VR3.2 ; VR3.2@53.126,14.213 55.601,14.213 C23.1 58.164,14.189 L1.2
NetC24_1: C24.1 R26.2 U15.8 | length 6.7
  BottomLayer w0.35: U15.8 11.075,26 12.874,24.201 C24.1
  BottomLayer w0.5: R26.2 13.828,25.871 C24.1
NetC29_2: C29.2 C30.1 R20.2 U5.5 | length 22.5
  TopLayer w0.3: v1(5.525,14.225) 5.975,13.775 10.825,13.775 16.3,19.25 v1(16.575,19.25)
  BottomLayer w0.3: v1(5.525,14.225) 3.625,14.225 3.151,14.699 C29.2 R20.2 6.4,16.947 C30.1 ; v1(16.575,19.25) 16.839,18.986 U5.5
NetC30_2: C30.2 C31.1 R25.2 U5.6 | length 19.5
  TopLayer w0.3: v1(6.701,14.549) 10.724,14.549 16.2,20.025 v1(17.225,20.025)
  BottomLayer w0.3: v1(6.701,14.549) C30.2 R25.2 10.209,15.423 C31.1 ; v1(17.225,20.025) 17.489,19.761 U5.6
NetF10_1: F10.1 R41.2 T1.1 U12.13 U12.18 ZD14.1 ZD15.1 | length 26.1
  BottomLayer w0.5: U12.13 33.785,15.84 35.225,14.4 39.125,14.4 40.135,15.41 U12.18 40.135,20.236 R41.2
  BottomLayer w0.8: R41.2 40.148,22.035 T1.1 40.162,24.867 F10.1 44.864,22.5 ZD15.1
NetF11_1: F11.1 R42.1 R76.1 U12.15 U12.17 ZD14.2 ZD16.2 | length 22
  BottomLayer w0.5: R42.1 R42.1@35.275,20.352 ; R76.1 36.753,20.276 36.751,20.274 36.325,19.848 U12.15 36.325,15.8 36.825,15.3 38.425,15.3 38.865,15.74 U12.17
  BottomLayer w0.6: ZD16.2 30.854,22.475 F11.1 35.042,24.867 35.197,25.022 R42.1 R76.1@36.751,20.274
NetLED2_1: LED2.1 R2.2 | length 20.8
  TopLayer w0.4: LED2.1 49.125,39.9 49.125,37.275 50,36.4 50,23.575 v1(51.224,22.351)
  BottomLayer w0.5: R2.2 v1(51.224,22.351)
NetP1_2: P1.2 R13.2 | length 1.8
  BottomLayer w0.6: P1.2 55.341,-0.423 R13.2
NetQ6_1: Q6.1 R11.2 | length 1.9
  BottomLayer w0.4: Q6.1 47.004,8.421 R11.2
NetR8_2: R8.2 U6.8 | length 3.1
  BottomLayer w0.3: R8.2 53.563,9.775 U6.8
NetR20_1: R20.1 U15.12 | length 4.9
  BottomLayer w0.3: R20.1 4.876,17.947 5.329,18.4 7.25,18.4 7.65,18.8 U15.12
NetR23_1: R23.1 U1.10 | length 12.4
  BottomLayer w0.3: U1.10 6.505,-3.18 7.075,-3.75 16.486,-3.75 R23.1
NetR25_1: R25.1 U15.11 | length 2.7
  BottomLayer w0.3: U15.11 8.3,17.098 R25.1
NetR76_2: R76.2 T1.2 | length 1.8
  BottomLayer w0.5: R76.2 38.638,20.437 T1.2
PH-INP: C19.1 J1.2 R21.1 | length 4.8
  BottomLayer w0.4: J1.2 11.65,33.655 R21.1@11.65,28.899
PH-VCM: C21.1 J2.3 R26.1 | length 40.8
  BottomLayer w0.5: 5.15,31.5 4.425,32.225 4.425,35.65 5.525,36.75 13.8,36.75 14.6,35.95 14.6,31.75 13.971,31.121 13.971,27.592 13.904,27.525 R26.1 12.972,27.422 12.6,27.05 10.2,27.05
  BottomLayer w0.6: R26.1@13.904,27.525 19.675,27.525 21.715,29.565 J2.3
RS485+: F10.2 GDT1.2 GDT2.2 J3.2 | length 9.4
  BottomLayer w0.5: J3.2 41.525,33.155 GDT2.2 ; F10.2 42.433,26.767 41.525,27.675 GDT2.2 ; GDT1.2 GDT2.2
RS485-: F11.2 GDT2.1 GDT3.1 J3.3 | length 10.9
  BottomLayer w0.5: F11.2 33.404,26.925 34.5,26.925 35.775,28.2 GDT3.1 35.8,30.05 GDT2.1 37.725,32.915 J3.3
RST#: C8.1 J9.15 R14.2 U2.4 | length 45.6
  TopLayer w0.3: v1(48.1,-5.155) 52.745,-5.155 v1(52.75,-5.15)
  BottomLayer w0.3: C8.1 45.012,-8.824 R14.2 45.037,-8.218 v1(48.1,-5.155) 48.5,-4.755 U2.4 ; v1(52.75,-5.15) 59.1,-5.15 64.075,-0.175 65.775,-0.175 70.275,4.325 74.125,4.325 77.645,7.845 J9.15
RX485: U2.10
SCK1: R10.2 U1.4 U2.12 | length 43.7
  TopLayer w0.3: v1(37.675,-7.8) 37.675,-6.125 v1(38.35,-5.45)
  BottomLayer w0.3: U1.4 10.315,-8.86 12.3,-6.875 21.4,-6.875 22.775,-5.5 38.325,-5.5 42.35,-1.475 U2.12 ; R10.2 v1(37.675,-7.8)
SPI_CS: U1.14 U5.3 | length 25.5
  BottomLayer w0.25: U1.14 11.585,0.34 9.1,2.825 7.825,2.825 7.075,3.575 7.075,6.293 15.539,14.757 U5.3
SPI_DIN: U1.12 U5.16 | length 19.9
  TopLayer w0.25: v3(7.875,4.925) 6.975,4.025 6.975,0.075 7.275,-0.225 8.1,-0.225 v3(9.025,0.7)
  BottomLayer w0.25: v3(7.875,4.925) 7.875,5.925 13.979,12.029 U5.16 ; v3(9.025,0.7) 9.045,0.68 U1.12
SPI_DOUT: U1.11 U5.15 | length 17.2
  TopLayer w0.25: v3(7.725,0.625) 7.725,3.675 v3(8.05,4)
  BottomLayer w0.25: U1.11@7.725,-1.429 U1.11 7.775,0.575 v3(7.725,0.625) ; v3(8.05,4) 8.825,4.775 8.825,6.075 13.25,10.5 14.375,10.5 14.911,11.036 U5.15
SPI_SCLK: U1.13 U5.1 | length 25.2
  BottomLayer w0.3: U1.13 10.315,0.51 9.1,1.725 7.35,1.725 6.4,2.675 6.4,6.725 14.239,14.564 U5.1
SSEL1: R12.2 U1.3 U2.11 | length 41.4
  BottomLayer w0.25: U1.3 11.585,-8.94 13.05,-7.475 21.75,-7.475 23,-6.225 39.15,-6.225 39.5,-5.875 ; R12.2 39.5,-5.875 ; U2.11 43.4,-1.975 39.5,-5.875
TP+: J2.1 R3.1 U5.4 | length 29.4
  TopLayer w0.5: v1(20.125,18.05) 21.075,19 21.075,24.2 v1(22.7,25.825) 23.05,26.175 24.35,26.175 J2.1
  BottomLayer w0.3: U5.4 16.189,16.736 16.375,16.55 19.15,16.55
  BottomLayer w0.4: 19.15,16.55 20.125,17.525 v1(20.125,18.05)
  BottomLayer w0.5: R3.1 21.288,24.413 v1(22.7,25.825)
TP-: J2.2 R18.1 R19.2 U5.11 | length 30.1
  BottomLayer w0.3: U5.11 17.511,14.836 18.375,15.7 18.925,15.7
  BottomLayer w0.4: 18.925,15.7 19.4,15.7 21.525,17.825
  BottomLayer w0.5: 21.525,17.825 22.9,17.825 24.05,18.975 24.05,23.2 ; R18.1 22.926,21.647 R19.2 23.763,22.913 24.05,23.2 ; J2.2 26.795,28.725 24.475,26.405 24.475,23.625 24.05,23.2
TX485: U2.9
VCC3.3: C3.2 C10.1 C11.1 C12.1 C13.1 C43.1 C44.1 CA1.1 CA13.1 CA14.1 FB7.2 J9.1 J9.2 P3.1 P3V3.1 R1.1 R2.1 R4.1 R5.1 R6.1 R7.2 R9.1 R10.1 R12.1 R13.1 R14.1 R17.1 R22.1 U1.1 U2.1 U2.6 U2.19 U2.27 U12.2 U12.8 | length 214.4
  TopLayer w0.5: v1(74.851,17.976) 75.824,17.976
  TopLayer w0.6: 45.925,2.55 45.95,2.575 v1(45.95,3.425) ; 49.2,3.25 49.324,3.126 v1(52.525,3.126)
  TopLayer w0.8: v1(66.337,-8.838) v1@66.45,-8.725 ; v1(74.801,20.501) 75.85,19.452
  TopLayer w1: v1@34.036,0.636 v1(38.889,0.636) 40.311,0.636 41.576,1.901 ; P3V3.1 49.2,3.25 48.5,2.55 45.925,2.55 42.225,2.55 41.576,1.901 ; v1(57.999,-0.426) 57.074,-0.426 56.3,-1.2 56.3,-5.85 55.25,-6.9 ; v1@66.45,-8.725 66.45,-6.175 ; J9.2 J9.1 76.975,25.625 75.85,24.5 75.85,19.452 75.85,9.375 72.6,6.125 69.375,6.125 66.45,3.2 66.45,-6.175 ; 41.576,1.901 41.576,-7.849 v1(42.526,-8.799) 44.425,-6.9 55.25,-6.9 ; 55.25,-6.9 65.725,-6.9 66.45,-6.175
  BottomLayer w0.3: C11.1 47.5,-4.343 U2.6 ; C13.1 45.279,4.151 46,3.43 U2.19 ; FB7.2 47.086,11.939 46.525,12.5 46.525,13.525 46.163,13.887 R7.2 45.349,14.999 45.85,15.5 48.15,15.5 51.224,18.574 v1(51.224,18.799) ; U2.1 50,-3.85 v1(53.138,-6.988) C10.1 ; U2.27 50,2.85 50.276,3.126 v1(52.525,3.126) C12.1
  BottomLayer w0.5: U12.8 33.785,2.191 CA14.1 ; CA13.1@38.894,2.231 40.155,3.491 ; R14.1 43.513,-8.33 C11.1 ; v1(51.224,18.799) R2.1 ; R13.1 v1(57.999,-0.426) ; R1.1 v1(66.337,-8.838) ; v1(74.801,20.501) R5.1 R4.1 ; v1(74.851,17.976) R17.1 ; R22.1 v1(75.803,11.378)
  BottomLayer w0.6: U1.1 14.887,-11.512 C3.2 18.251,-11.512 CA1.1 ; P3.1 29.2,-11.025 29.75,-10.475 v1(32.775,-10.475) R9.1 R6.1 R10.1 R12.1 40.3,-10.475 41.976,-8.799 v1(42.526,-8.799) R14.1 ; CA13.1 40.413,3.549 C43.1 40.413,4.913 41.405,5.905 U12.2
  BottomLayer w0.8: CA1.1 22.361,-11.761 22.85,-12.25 P3.1 ; v1(33.976,0.576) CA14.1 ; v1(38.889,0.636) CA13.1
  BottomLayer w1: CA14.1@33.725,1.749 CA14.1 ; FB7.2 49.2,11.364 P3V3.1
VCC_COM: C45.1 C46.2 CA15.1 CA16.1 R41.1 U12.12 U12.19 | length 32.7
  BottomLayer w0.5: CA15.1@26.3,16.039 CA15.1 26.701,16.013 29.437,16.013 29.875,15.575 32.15,15.575 ; U12.12 32.515,15.94 32.15,15.575 ; R41.1 41.405,19.982 U12.19 41.405,15.97 ; CA16.1 46.386,17.963 C46.2 44.826,16.676 43.475,15.325 42.05,15.325 41.405,15.97 ; 32.15,15.575 34.2,13.525 40.45,13.525 41.405,14.48 41.405,15.97
  other v1: 29.9,15.575 45.85,17.95 41.375,18.925
VDD_ISO: C2.1 C6.1 C14.1 C25.1 CA2.1 FB1.1 R23.2 U1.16 U5.13 U7.3 U15.1 U15.14 | length 65.8
  TopLayer w0.8: v1(4.2,21) v1@4.275,20.925 ; v1(5.8,20.925) v1@4.275,20.925 ; v1(16.675,2) 16.675,3.175 15.375,4.475 10.3,4.475 4.35,10.425 4.35,20.85 v1@4.275,20.925 ; v1(18.475,2.05) 18.475,5.575 19.475,6.575 v1(19.475,9.9)
  BottomLayer w0.3: U5.13 16.211,10.789 17.701,9.299 FB1.1
  BottomLayer w0.4: v1(5.8,20.925) 6.1,20.925 6.35,20.675 U15.14 ; CA2.1@15.336,2.1 CA2.1@15.336,2.514
  BottomLayer w0.5: v1(4.2,21) 4.2,24.725 3.838,25.087 C25.1 3.076,25.551 3.525,26 U15.1 ; CA2.1 15.336,1.948 14.125,0.737 U1.16 14.534,-1.888 R23.2 ; CA2.1@15.336,2.1 15.4,2.036 CA2.1@15.4,2.012 ; C6.1 C6.1@19.415,2.026 ; U7.3 U7.3@21.268,2.026
  BottomLayer w0.8: CA2.1@15.4,2.012 C2.1 C6.1 ; FB1.1 C14.1 19.475,9.061 v1(19.475,9.9) ; C6.1@19.415,2.026 U7.3@21.268,2.026
VREF: C33.1 C35.1 FB2.2 U5.9 U15.9 | length 27.4
  TopLayer w0.5: v1(14.725,20.2) 15.475,20.95 17.8,20.95 18.3,20.45 18.3,16.525 20.75,14.075 v1(20.75,11.2)
  BottomLayer w0.3: C35.1@20.711,12 20.75,12.039 C35.1
  BottomLayer w0.35: U15.9 11.336,19.6 C33.1 ; U5.9@18.811,12 C35.1@20.711,12
  BottomLayer w0.5: C33.1 14.538,20.013 v1(14.725,20.2) ; C35.1@20.75,12 v1(20.75,11.2) 20.75,9.875 21.524,9.101 FB2.2 ; C35.1@20.75,12.039 C35.1@20.75,12.05
pads on no net: J9.11 J9.17 J9.19 P3.4 U1.7 U2.7 U2.15 U2.16 U2.20 U2.32 U2.33 U2.34 U5.2 U6.7 U6.9 U15.2 U15.3 U15.7

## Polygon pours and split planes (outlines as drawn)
VDD_ISO on TopLayer "TopLayer-No Net 1" (hatched 90Degree grid 0.3 track 0.3, remove dead copper, pour order 16): 19.125,1.475 19.125,4.95 19.2,5.025 11.275,5.025 8.375,7.925 4.9,11.4 4.9,20.125 4.9,21.625 3.1,21.625 3.05,21.575 3.05,10.7 10.125,3.625 12.275,1.475 18.9,1.475
GND on TopLayer "TopLayer-No Net 1" (hatched 90Degree grid 0.3 track 0.3, remove dead copper, pour order 15): 3.7,-7.675 21.25,-7.675 26.175,-2.75 27.1,-1.825 27.1,10.3 27.1,10.975 27.375,11.25 49.3,11.25 55.75,4.8 59.625,0.925 59.625,-13.9 3.8,-13.9 3.7,-14
VCC3.3 on TopLayer "TopLayer-No Net 1" (hatched 90Degree grid 0.3 track 0.3, remove dead copper, pour order 12): 42.996,-6.15 66.826,-6.15 66.826,-8 66.85,-8.025 44.951,-8.025 43.534,-9.475 43.363,-9.65 42.819,-9.65 42.819,-6.15
VCC3.3 on TopLayer "TopLayer-No Net 1" (hatched 90Degree grid 0.3 track 0.3, remove dead copper, pour order 9): 48.819,2.05 44,2.05 43.4,1.45 43.325,1.375 43.325,-4.175 43.325,-9.575 43.25,-9.65 40.925,-9.65 40.9,-9.625 40.9,-0.875 40.625,-0.6 40.3,-0.275 32.975,-0.275 32.975,1.925 33.025,1.975 39.65,1.975 41.05,3.375 48.819,3.375
VCC3.3 on TopLayer "BottomLayer-No Net" (hatched 90Degree grid 0.3 track 0.3, remove dead copper, pour order 13): 48.525,10.475 50.053,10.475 51.187,9.25 51.65,8.75 51.65,2.05 48.618,2.05 48.548,1.975
GND_ISO on TopLayer "BottomLayer-No Net 1" (hatched 90Degree grid 0.3 track 0.3, remove dead copper, pour order 11): 4.175,-4.575 19.3,-4.575 24.425,0.55 24.55,0.675 24.55,10.1 24.55,11.5 21.75,14.3 13.9,14.3 11.225,14.3 4.175,7.25
GND on BottomLayer "TopLayer-No Net 1" (hatched 90Degree grid 0.3 track 0.3, remove dead copper, pour order 14): 3.775,-7.575 21.325,-7.575 26.25,-2.65 27.175,-1.725 27.175,10.4 27.175,11.075 27.45,11.35 49.375,11.35 55.825,4.9 59.7,1.025 59.7,-13.8 3.875,-13.8 3.775,-13.9
GND_ISO on BottomLayer "BottomLayer-No Net 1" (hatched 90Degree grid 0.3 track 0.3, remove dead copper, pour order 10): 4.3,-4.675 19.425,-4.675 24.55,0.45 24.675,0.575 24.675,10 24.675,11.4 21.875,14.2 14.025,14.2 11.35,14.2 4.3,7.15

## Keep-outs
KeepOutLayer:
  lines w0.3: 15.625,30.05 15.625,45.975 ; 15.65,30.05 ccw(c17.368,30.588) 19.086,30.05 ; 19.072,30 19.072,45.7 ; 23.5,29.325 23.5,46.55 ; 23.525,29.325 ccw(c24.138,29.517) 24.75,29.325 24.75,46.475
  lines w0.5: -5.32,31.4 -12.6,31.4 -12.6,-1.475 -5.257,-1.475 ; -5.181,31.426 ccw(c-5.32,36.194) -0.552,36.055 ; -5.117,-1.525 cw(c-5.257,-6.33) -0.452,-6.19 ; -0.55,36.194 -0.55,43.65 72.9,43.65 72.9,36.034 ; -0.45,-6.33 -0.45,-13.825 72.8,-13.825 72.8,-6.31 ; 72.919,-6.177 cw(c77.477,-6.31) 77.344,-1.752 ; 72.966,35.91 ccw(c77.223,36.034) 77.099,31.777 ; 77.223,31.775 84.875,31.775 84.875,-1.75 77.477,-1.75

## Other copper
BottomLayer:
  pour cut-out: 58.05,16.7 61.65,16.7 61.675,16.675 61.675,12.875 61.7,12.85 58.025,12.85

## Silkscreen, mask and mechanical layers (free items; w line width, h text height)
TopOverlay:
  lines w0.2: 27.38,-13.5 50,-13.5 50,26.595 27.38,26.595 27.38,-13.5
  lines w0.3: 26.775,37.525 26.775,38.5 ; 32.025,37.5 32.025,38.4 ; 35.125,37.525 35.125,38.2 ; 42.95,37.5 42.95,38.05 ; 51.55,37.475 51.55,38.05 ; 57.75,37.55 57.75,38.1
  text "GUARD  INP" at 4.825,38.625 h1
  text "VCM    Temper" at 20.875,38.625 h1
  text "+ 24V -    PE" at 51.525,38.35 h1
  text "- RS485 +   PE" at 35.25,38.3 h1
  text "SPLora module" at 30.375,11.9 h1
  text "SPMsensor_RS485 V0.7" at -5.825,7.975 h1.2 r90
  text "JTAG" at 76.325,5.525 h0.8 r270
Mechanical1:
  lines w0.2: 24.826,25.301 43.054,25.301
  lines w0.25: -14.675,30 75.525,30 ; -13.9,33.675 76.3,33.675 ; -13.65,0 87.15,0 ; -0.025,-4.875 -0.025,36.625 ; 72.45,-5.025 72.45,45.8
  lines w0.254: -13.425,43.65 86.675,43.65 ; -12.596,-13.814 87.914,-13.814 ; 6.475,26.45 6.475,42.85 ; 84.875,-12.675 84.875,46.95
  lines w0.3: -12.594,-18.55 -12.594,55.4 ; 29.2,-13.175 29.2,29.35 ; 55.7,-30.025 55.7,46.1

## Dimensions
40.297,-12.224 to 46.239,25.301 on Mechanical1
-14.225,15 to -13.625,0 on Mechanical1
-13.675,-13.816 to -14.65,15 on Mechanical1
-0.025,-3.2 to 72.45,-3.875 on Mechanical1
-12.596,-13.814 to 84.875,-12.675 on Mechanical1
-12.596,-13.814 to -13.425,43.65 on Mechanical1
6.475,42.325 to -0.025,36.625 on Mechanical1
-13.475,43.675 to -13.2,33.675 on Mechanical1
-14.225,30 to -13.625,15 on Mechanical1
